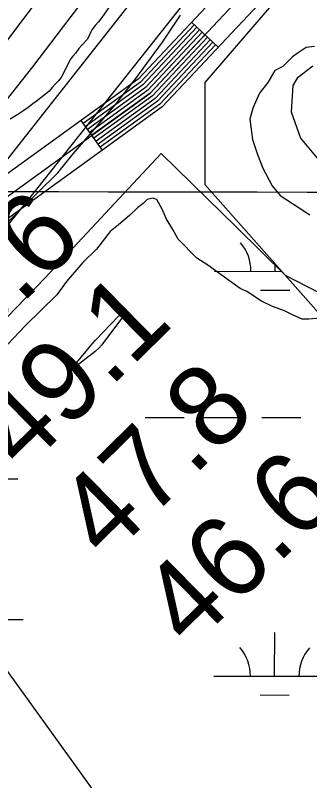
# Model space of a CAD drawing. Extents: x 3208593 to 3246461, y 812903 to 838290.
# Drawn here: x 3215454 to 3215696, y 829962 to 830591 of the extents above; entities that cross this region are included whole.
import ezdxf

# ---------------------------------------------------------------- set-up
doc = ezdxf.new("R2010")
doc.units = 0
for name, color, linetype in [('V-GRID-MAJR', 7, 'Continuous'), ('V-RIVR-RANG', 7, 'Continuous'), ('V-ROAD-CNTR', 7, 'Continuous'), ('V-SITE-VEGE', 7, 'Continuous'), ('V-TOPO-MAJR', 7, 'Continuous'), ('V-TOPO-MINR', 7, 'Continuous'), ('V-TOPO-SHOR', 7, 'Continuous'), ('V-WETL-SWMP', 7, 'Continuous')]:
    doc.layers.add(name, color=color, linetype=linetype)

msp = doc.modelspace()

# ---------------------------------------------------------------- linework, layer by layer
at = {"layer": 'V-GRID-MAJR'}
msp.add_spline([(3212790.146, 830450.674), (3218024.231, 830441.158), (3223258.319, 830432.403), (3228492.407, 830424.409), (3233726.4960000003, 830417.177), (3238960.5870000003, 830410.706), (3244194.678, 830404.996), (3244194.679, 830404.996)], degree=3, dxfattribs=at)
at = {"layer": 'V-RIVR-RANG'}
msp.add_line((3215578.4224, 829870.1206999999), (3214874.8604, 830842.2320999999), dxfattribs=at)
at = {"layer": 'V-ROAD-CNTR'}
for p, q in [((3215620.428722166, 830564.293843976), (3215598.562765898, 830584.8338028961)), ((3215525.220912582, 830479.800012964), (3215507.655947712, 830504.119964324))]:
    msp.add_line(p, q, dxfattribs=at)
for points in [[(3216314.591333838, 830928.8731148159), (3216093.0897768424, 830852.4042677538), (3215817.053328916, 830772.778427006), (3215718.594525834, 830712.609547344), (3215554.569853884, 830538.00189656), (3215364.9292331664, 830401.0401704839), (3215183.906595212, 830230.6655112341), (3215082.6847976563, 830100.1397722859), (3214993.008977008, 829972.525027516)], [(3212784.03739496, 828348.8552748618), (3213009.8549433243, 828462.8960467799), (3213347.6612677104, 828626.5207195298), (3213606.2947504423, 828811.2593500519), (3213843.814275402, 828911.5451494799), (3214091.8917792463, 829054.057864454), (3214266.073430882, 829244.0734844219), (3214392.751177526, 829391.8641888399), (3214603.8797552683, 829486.871998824), (3214720.000523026, 829566.045840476), (3214888.904185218, 829798.2883759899), (3215094.754773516, 830091.2267901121), (3215195.041572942, 830220.546531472), (3215374.5012140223, 830389.4501936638), (3215564.517833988, 830526.6839191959), (3215728.142506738, 830700.865570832), (3215823.15131672, 830758.9254547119), (3216097.618767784, 830838.0992963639), (3216319.3043244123, 830914.6311432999)], [(3216324.0173149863, 830900.3891717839), (3216102.147758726, 830823.7943249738), (3215829.249304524, 830745.0724824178), (3215737.6904876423, 830689.1215943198), (3215574.465814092, 830515.3659418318), (3215384.073194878, 830377.8602168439), (3215206.176550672, 830210.4275517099), (3215106.824749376, 830082.3138079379), (3214901.107160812, 829789.5643934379), (3214730.6005018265, 829555.11886233), (3214611.23874055, 829473.7350250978), (3214401.960159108, 829379.55921345), (3214277.2994084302, 829234.1215043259), (3214101.378760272, 829042.2088881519), (3213850.492262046, 828898.0821764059), (3213613.66073571, 828798.0873763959), (3213355.3452523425, 828613.57574542), (3213016.5059300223, 828449.4500736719), (3212783.7263955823, 828331.894308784)], [(3215600.7487615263, 830582.7788070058), (3215556.558849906, 830535.7389010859), (3215509.410944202, 830501.6869691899)], [(3215602.934757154, 830580.7248111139), (3215558.5488459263, 830533.4749056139), (3215511.1679406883, 830499.2549740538)], [(3215605.12175278, 830578.6708152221), (3215560.538841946, 830531.2109101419), (3215512.9239371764, 830496.8229789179)], [(3215607.3077484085, 830576.61681933), (3215562.527837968, 830528.9479146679), (3215514.680933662, 830494.3909837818)], [(3215609.494744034, 830574.562823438), (3215564.517833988, 830526.6839191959), (3215516.4369301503, 830491.958988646)], [(3215611.6817396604, 830572.5088275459), (3215566.507830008, 830524.4199237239), (3215518.1929266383, 830489.5269935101)], [(3215613.867735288, 830570.4548316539), (3215568.49682603, 830522.1569282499), (3215519.949923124, 830487.094998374)], [(3215616.054730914, 830568.400835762), (3215570.48682205, 830519.8929327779), (3215521.705919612, 830484.663003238)], [(3215618.240726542, 830566.34683987), (3215572.47681807, 830517.628937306), (3215523.462916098, 830482.231008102)]]:
    msp.add_lwpolyline(points, dxfattribs=at)
at = {"layer": 'V-SITE-VEGE'}
for p, q in [((3215530.542, 830596.921), (3215524.7630000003, 830588.714)), ((3215524.7630000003, 830588.714), (3215521.973, 830585.31)), ((3215574.578, 830568.572), (3215589.309, 830590.736)), ((3215521.973, 830585.31), (3215519.182, 830582.107)), ((3215516.591, 830578.505), (3215513.009, 830570.905)), ((3215519.182, 830582.107), (3215516.591, 830578.505)), ((3215513.009, 830570.905), (3215508.223, 830566.098)), ((3215508.223, 830566.098), (3215505.8310000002, 830563.294)), ((3215551.946, 830537.561), (3215574.578, 830568.572)), ((3215692.801, 830564.015), (3215686.061, 830559.622)), ((3215699.506, 830565.064), (3215692.801, 830564.015)), ((3215503.24, 830559.692), (3215500.846, 830557.089)), ((3215505.8310000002, 830563.294), (3215503.24, 830559.692)), ((3215686.061, 830559.622), (3215681.566, 830556.321)), ((3215498.6550000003, 830554.287), (3215493.4790000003, 830543.685)), ((3215500.846, 830557.089), (3215498.6550000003, 830554.287)), ((3215681.566, 830556.321), (3215673.677, 830548.5920000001)), ((3215666.947, 830545.3129999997), (3215661.268, 830535.329)), ((3215673.677, 830548.5920000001), (3215666.947, 830545.313)), ((3215491.489, 830539.884), (3215489.2970000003, 830536.8809999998)), ((3215493.4790000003, 830543.685), (3215491.489, 830539.884)), ((3215486.705, 830534.278), (3215483.913, 830531.2760000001)), ((3215489.2970000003, 830536.8809999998), (3215486.705, 830534.278)), ((3215536.1210000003, 830517.64), (3215551.946, 830537.561)), ((3215661.268, 830535.329), (3215654.485, 830526.4709999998)), ((3215481.3200000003, 830528.274), (3215478.529, 830525.669)), ((3215483.913, 830531.2760000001), (3215481.3200000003, 830528.274)), ((3215654.485, 830526.4709999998), (3215648.7770000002, 830514.255)), ((3215470.747, 830519.658), (3215467.951, 830517.853)), ((3215478.529, 830525.669), (3215470.747, 830519.658)), ((3215464.162, 830514.8469999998), (3215460.568, 830512.443)), ((3215467.951, 830517.853), (3215464.162, 830514.8469999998)), ((3215513.535, 830491.0920000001), (3215536.1210000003, 830517.64)), ((3215648.7770000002, 830514.255), (3215646.457, 830505.3539999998)), ((3215455.7800000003, 830509.035), (3215449.392, 830505.225)), ((3215460.568, 830512.443), (3215455.7800000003, 830509.035)), ((3215646.457, 830505.3539999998), (3215648.515, 830488.5979999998)), ((3215501.114, 830476.711), (3215513.535, 830491.0920000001)), ((3215648.515, 830488.5979999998), (3215652.853, 830476.279)), ((3215488.683, 830461.22), (3215501.114, 830476.711)), ((3215652.853, 830476.279), (3215657.203, 830465.079)), ((3215657.203, 830465.079), (3215664.862, 830450.495)), ((3215424.441, 830398.279), (3215488.683, 830461.22)), ((3215664.862, 830450.495), (3215671.477, 830442.6159999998)), ((3215562.098, 830439.2719999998), (3215558.718, 830435.958)), ((3215566.5700000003, 830440.3409999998), (3215562.098, 830439.2719999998)), ((3215569.909, 830439.192), (3215566.5700000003, 830440.3409999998)), ((3215574.291, 830431.336), (3215569.909, 830439.192)), ((3215671.477, 830442.6159999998), (3215686.995, 830432.415)), ((3215554.221, 830432.657), (3215547.4590000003, 830426.0310000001)), ((3215558.718, 830435.958), (3215554.221, 830432.657)), ((3215686.995, 830432.415), (3215695.863, 830426.7459999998)), ((3215547.4590000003, 830426.0310000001), (3215538.453, 830418.3119999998)), ((3215577.558, 830423.4940000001), (3215574.291, 830431.336)), ((3215583.045, 830414.509), (3215577.558, 830423.4940000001)), ((3215531.703, 830412.8030000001), (3215520.398, 830398.4139999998)), ((3215538.453, 830418.3119999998), (3215531.703, 830412.8030000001)), ((3215587.427, 830406.655), (3215583.045, 830414.509)), ((3215602.8880000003, 830390.877), (3215587.427, 830406.655)), ((3215520.398, 830398.4139999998), (3215509.128, 830387.3690000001)), ((3215509.128, 830387.3690000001), (3215495.5810000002, 830371.89)), ((3215611.755, 830385.207), (3215602.8880000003, 830390.877)), ((3215622.8310000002, 830377.285), (3215611.755, 830385.207)), ((3215638.336, 830365.9679999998), (3215622.8310000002, 830377.285)), ((3215495.5810000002, 830371.89), (3215487.657, 830360.8129999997)), ((3215643.893, 830363.68), (3215638.336, 830365.9679999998)), ((3215656.0840000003, 830355.7440000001), (3215643.893, 830363.68)), ((3215487.657, 830360.8129999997), (3215461.735, 830335.416)), ((3215664.965, 830351.1909999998), (3215656.0840000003, 830355.7439999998)), ((3215674.971, 830347.74), (3215664.965, 830351.1909999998)), ((3215681.629, 830344.326), (3215674.971, 830347.74)), ((3215689.4050000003, 830340.8979999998), (3215681.629, 830344.3259999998)), ((3215694.984, 830340.8429999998), (3215689.4050000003, 830340.8979999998)), ((3215716.203, 830342.8579999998), (3215694.984, 830340.8429999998)), ((3215461.735, 830335.416), (3215447.072, 830319.9469999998))]:
    msp.add_line(p, q, dxfattribs=at)
at = {"layer": 'V-TOPO-MAJR'}
msp.add_lwpolyline([(3214958.5156072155, 829959.1537098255), (3215043.3379101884, 830052.6545933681), (3215127.127113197, 830147.0823846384), (3215210.2275828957, 830242.1281143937), (3215379.9533724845, 830438.4184097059), (3215385.1327350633, 830444.4840541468), (3215390.26132691, 830450.5917959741), (3215395.313762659, 830456.7626838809), (3215400.315427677, 830462.9756691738), (3215442.165720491, 830515.626661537), (3215467.8579613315, 830548.3466512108), (3215493.288315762, 830581.2664741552), (3215518.325840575, 830614.4860470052), (3215543.1014789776, 830647.905453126), (3215609.320870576, 830738.3455113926), (3215664.4167301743, 830813.4294953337), (3215719.61652428, 830888.4368244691), (3215774.9722201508, 830963.3291713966), (3215830.4318505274, 831038.1448635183)], dxfattribs=at)
at = {"layer": 'V-TOPO-MINR'}
for points in [[(3214734.000507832, 829671.4548660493), (3215089.1431570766, 830060.086119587), (3215143.958381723, 830120.6014362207), (3215198.416237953, 830181.4338586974), (3215252.338041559, 830242.7419399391), (3215305.9024767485, 830304.3671270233), (3215381.54346834, 830392.1664255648), (3215396.896456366, 830410.2309971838), (3215412.085676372, 830428.4303952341), (3215427.029244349, 830446.8320329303), (3215441.8090443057, 830465.3684970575), (3215557.5593945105, 830612.5557201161), (3215629.826156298, 830704.99156496), (3215701.7391634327, 830797.7001987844), (3215773.1215385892, 830890.8180160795), (3215844.1501590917, 830984.2086223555), (3216014.290256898, 831209.2447959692)], [(3214898.7171396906, 829930.2984672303), (3214951.104858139, 829988.4516545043), (3215003.0175797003, 830047.0380766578), (3215217.404937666, 830292.0102889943), (3215236.420828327, 830313.7154134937), (3215255.452291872, 830335.4068599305), (3215274.507114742, 830357.0777892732), (3215293.577510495, 830378.7350405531), (3215311.2299046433, 830398.7601813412), (3215321.431576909, 830410.4409304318), (3215331.560988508, 830422.1834364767), (3215341.5820091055, 830434.0185779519), (3215351.530769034, 830445.9154763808), (3215361.34224266, 830457.9244005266), (3215371.0429904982, 830470.0208854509), (3215380.5776496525, 830482.2487115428), (3215390.0015830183, 830494.5640984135), (3215715.1054808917, 830925.4818296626), (3215762.8377604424, 830989.2440336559), (3215810.2503192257, 831053.2412585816)], [(3215015.6307617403, 829899.5018509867), (3215072.917089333, 829968.3623171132), (3215129.370565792, 830037.9286291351), (3215183.0199198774, 830105.2888592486), (3215212.263180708, 830141.5051305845), (3215241.825753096, 830177.4552195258), (3215271.8672928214, 830213.0060348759), (3215302.2281441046, 830248.2906678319), (3215326.510228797, 830276.1312801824), (3215344.939925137, 830297.3215447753), (3215363.3300278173, 830318.5460188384), (3215381.6607400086, 830339.8218071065), (3215399.951858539, 830361.1318048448), (3215418.0896360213, 830382.5692820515), (3215436.062602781, 830404.1424809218), (3215453.788353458, 830425.9192622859), (3215471.3492934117, 830447.8317653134), (3215885.284230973, 830970.4184611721), (3215920.3333253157, 831014.8066917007)], [(3215541.2833212, 830342.4993869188), (3215541.232481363, 830341.9711646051), (3215541.0097676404, 830341.4165523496), (3215524.701550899, 830319.8413542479), (3215522.2015428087, 830316.9516048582), (3215519.343146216, 830314.4158089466), (3215504.4628270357, 830302.8741715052), (3215503.8362763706, 830302.805354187), (3215503.4049032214, 830302.9355632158), (3215503.266296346, 830303.3643117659), (3215503.322866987, 830303.9920866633), (3215505.10893332, 830306.346392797), (3215506.922267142, 830308.6791137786), (3215508.7765021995, 830310.9794570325), (3215510.6580047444, 830313.2582151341), (3215515.782524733, 830319.3542808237), (3215517.68161405, 830321.5386408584), (3215519.65226467, 830323.6586656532), (3215538.4724436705, 830343.242253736), (3215539.5462961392, 830343.7599851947), (3215540.6975053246, 830343.4502717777), (3215541.2833212, 830342.4993869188)]]:
    msp.add_lwpolyline(points, dxfattribs=at)
at = {"layer": 'V-TOPO-SHOR'}
msp.add_lwpolyline([(3216413.4279908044, 830882.0463151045), (3216113.584547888, 830834.5185837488), (3215861.6351237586, 830738.9572955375), (3215681.5964968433, 830619.3094598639), (3215609.5287193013, 830535.4774847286), (3215609.4066234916, 830451.540856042), (3215705.177218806, 830343.4827953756), (3215801.0001408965, 830271.3975755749), (3215848.8592751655, 830199.3821248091), (3215884.640251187, 830067.429381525), (3216004.4276249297, 829983.318330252), (3216052.3390859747, 829947.275720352), (3216136.118734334, 829839.235101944), (3216207.9772047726, 829779.1757136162), (3216339.807852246, 829731.0200609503)], dxfattribs=at)
at = {"layer": 'V-WETL-SWMP'}
for p, q in [((3215698.0904467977, 830548.7785320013), (3215685.4194445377, 830539.0365386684)), ((3215685.4194445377, 830539.0365386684), (3215681.862442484, 830532.8815447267)), ((3215681.862442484, 830532.8815447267), (3215680.320433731, 830511.2645705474)), ((3215680.320433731, 830511.2645705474), (3215688.0974236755, 830489.6666002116)), ((3215688.0974236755, 830489.6666002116), (3215707.3784114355, 830466.7036363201)), ((3215573.5105788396, 830477.1351924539), (3215477.7507959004, 830374.5205021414)), ((3215635.70056843, 830416.1872231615), (3215573.5105788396, 830477.1351924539)), ((3215675.836040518, 830376.8107805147), (3215635.70056843, 830416.1872231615)), ((3215667.311608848, 830380.1087670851), (3215667.3189684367, 830385.1667804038)), ((3215617.311665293, 830380.1814979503), (3215672.482147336, 830380.1012459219)), ((3215704.0226513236, 830362.1949286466), (3215675.836040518, 830376.8107805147)), ((3215477.7507959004, 830374.5205021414), (3215341.790567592, 830233.7471756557)), ((3215655.2891697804, 830364.6952482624), (3215679.289142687, 830364.6603374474)), ((3215560.293022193, 830260.1933847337), (3215592.2929860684, 830260.1468369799)), ((3215608.2929680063, 830260.1235631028), (3215640.292931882, 830260.0770153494)), ((3215656.292913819, 830260.0537414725), (3215688.292877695, 830260.0071937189)), ((3215355.6274218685, 830209.7490725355), (3215455.62730898, 830209.6036108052)), ((3215428.051382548, 830094.2116717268), (3215460.0513464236, 830094.1651239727)), ((3215666.8275557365, 830047.4343226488), (3215666.8799369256, 830083.4342625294)), ((3215616.827612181, 830047.507053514), (3215716.8274992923, 830047.3615917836)), ((3215654.805116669, 830032.0208038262), (3215678.805089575, 830031.9858930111))]:
    msp.add_line(p, q, dxfattribs=at)
for centre, radius, start, end in [((3215612.0694259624, 830380.663926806), 35.24628790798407, 359.1448368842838, 40.688495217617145), ((3215611.585372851, 830047.9894823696), 35.24628790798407, 359.1448368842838, 40.688495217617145), ((3215722.07112033, 830047.8287677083), 35.246287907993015, 139.14483304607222, 180.68849137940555)]:
    msp.add_arc(centre, radius, start, end, dxfattribs=at)

# ---------------------------------------------------------------- texts
at = {"layer": 'V-RIVR-RANG'}
for s, p in [('46.6', (3215386.9080013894, 830282.3011666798)), ('49.1', (3215460.1718579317, 830214.0937214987)), ('47.8', (3215528.7322511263, 830141.2650969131)), ('46.6', (3215597.6680013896, 830068.8061666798))]:
    msp.add_text(s, height=67, rotation=44.48832571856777, dxfattribs=at).set_placement(p)

doc.saveas('drawing.dxf')
